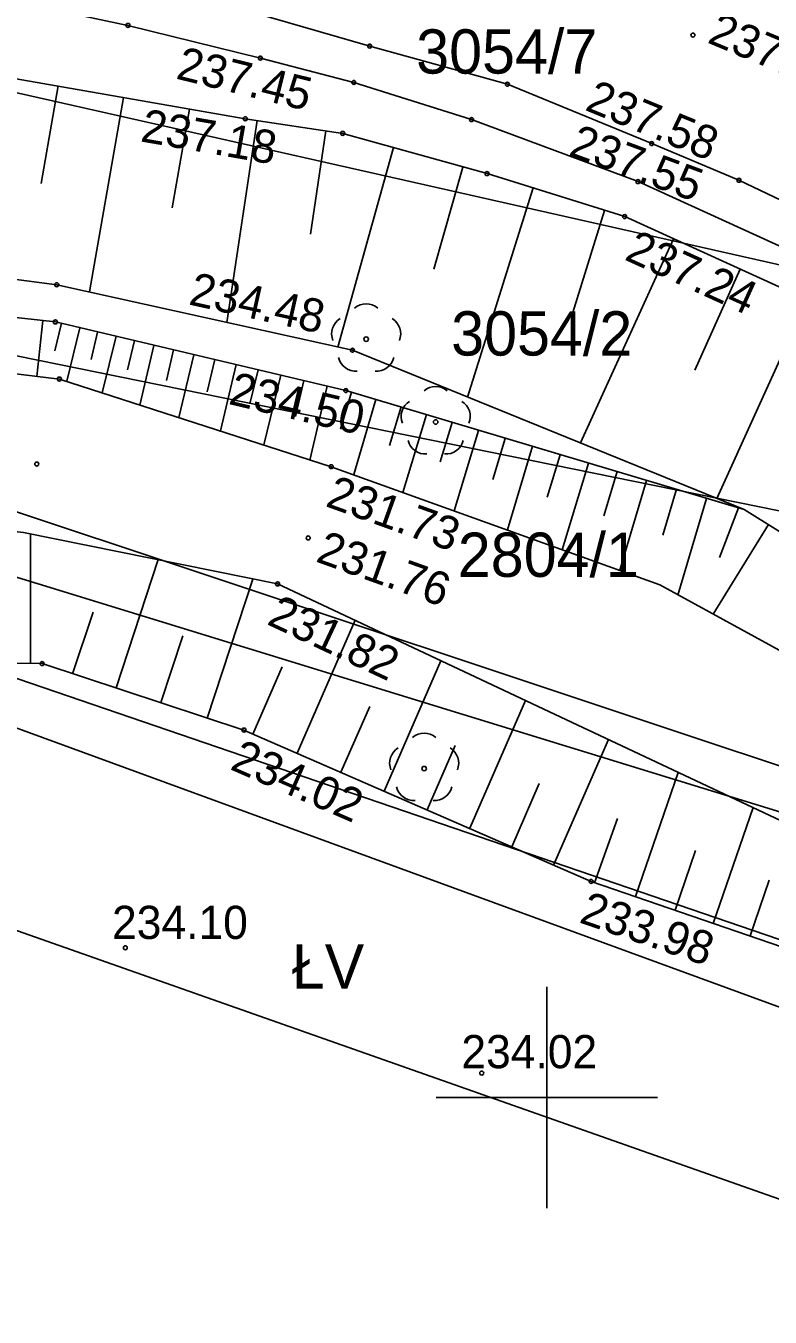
# Model space of a CAD drawing. Extents: x 6596400 to 6597200, y 5539751 to 5540251.
# Drawn here: x 6596788.23 to 6596805.04, y 5540046.04 to 5540075.21 of the extents above; entities that cross this region are included whole.
import ezdxf

# ---------------------------------------------------------------- set-up
doc = ezdxf.new("R2010")
doc.units = 0
for name, color, linetype in [('000 Inne (niezydentyfikowane)', 7, 'Continuous'), ('140-Punkty robocze', 7, 'Continuous'), ('209-oznaczenie konturu klasyfikacyjnego', 7, 'Continuous'), ('211-numer działki ewidencyjnej', 7, 'Continuous'), ('217-kontur klasyfikacyjny', 7, 'Continuous'), ('218-kontur użytku gruntowego', 7, 'Continuous'), ('219-działka ewidencyjna', 7, 'Continuous'), ('bariera ochronna', 7, 'Continuous'), ('drzewo liściaste', 7, 'Continuous'), ('jezdnia', 7, 'Continuous'), ('Linia obszaru zagospodarowania terenu', 7, 'Continuous'), ('pikieta sztuczna', 7, 'Continuous'), ('pikieta sztuczna-Atr2', 7, 'Continuous'), ('rów melioracyjny (poligon)', 7, 'Continuous'), ('skarpa umocniona', 7, 'Continuous'), ('Wstawianie ramki sekcyjnej z opisem', 7, 'Continuous'), ('Zakres', 7, 'Continuous')]:
    doc.layers.add(name, color=color, linetype=linetype)

# ---------------------------------------------------------------- blocks, each defined once
blk = doc.blocks.new('OP021')
blk.add_circle((0, 0), 0.05)
for centre, start, end in [((0, 0.4), 49.272, 130.728), ((-0.38, 0.124), 121.308, 202.548), ((0.38, 0.124), 337.452, 58.692), ((-0.235, -0.324), 193.221, 274.871), ((0.235, -0.324), 265.129, 346.779)]:
    blk.add_arc(centre, 0.4, start, end)
blk = doc.blocks.new('RAMKA500K')
for p, q in [((0, 48.5), (0, 53.5)), ((400, 48.5), (400, 53.5)), ((0, 51), (2.5, 51)), ((397.5, 51), (400, 51))]:
    blk.add_line(p, q)
blk = doc.blocks.new('PW01')
blk.add_circle((0, 0), 0.045)
blk = doc.blocks.new('PIKIETA')
blk.add_circle((0, 0), 0.045)

msp = doc.modelspace()

# ---------------------------------------------------------------- linework, layer by layer
at = {"layer": '000 Inne (niezydentyfikowane)'}
for p, q in [((6596788.96, 5540073.85), (6596788.58, 5540071.65)), ((6596790.44, 5540073.59), (6596789.67, 5540069.2)), ((6596791.93, 5540073.33), (6596791.54, 5540071.1)), ((6596793.46, 5540073.07), (6596792.77, 5540068.51)), ((6596795.01, 5540072.84), (6596794.66, 5540070.5)), ((6596796.54, 5540072.46), (6596795.28, 5540067.95)), ((6596798.1, 5540072.02), (6596797.45, 5540069.71)), ((6596799.69, 5540071.55), (6596798.21, 5540066.82)), ((6596801.3, 5540071.04), (6596800.55, 5540068.61)), ((6596802.86, 5540070.4), (6596800.76, 5540065.79)), ((6596804.37, 5540069.71), (6596803.34, 5540067.43)), ((6596805.88, 5540069.03), (6596803.84, 5540064.53)), ((6596788.62, 5540068.55), (6596788.48, 5540067.29)), ((6596789.04, 5540068.49), (6596788.89, 5540067.87)), ((6596789.45, 5540068.39), (6596789.16, 5540067.18)), ((6596789.85, 5540068.29), (6596789.71, 5540067.67)), ((6596790.27, 5540068.2), (6596789.96, 5540066.92)), ((6596790.69, 5540068.1), (6596790.53, 5540067.44)), ((6596791.12, 5540067.99), (6596790.81, 5540066.64)), ((6596791.57, 5540067.89), (6596791.41, 5540067.2)), ((6596792.03, 5540067.78), (6596791.69, 5540066.36)), ((6596792.5, 5540067.67), (6596792.33, 5540066.94)), ((6596792.98, 5540067.56), (6596792.63, 5540066.06)), ((6596793.48, 5540067.44), (6596793.29, 5540066.67)), ((6596793.99, 5540067.32), (6596793.61, 5540065.74)), ((6596794.51, 5540067.2), (6596794.32, 5540066.38)), ((6596795.04, 5540067.07), (6596794.65, 5540065.4)), ((6596795.59, 5540066.93), (6596795.34, 5540066.1)), ((6596796.14, 5540066.77), (6596795.64, 5540065.07)), ((6596796.71, 5540066.6), (6596796.45, 5540065.73)), ((6596797.28, 5540066.43), (6596796.75, 5540064.67)), ((6596797.86, 5540066.25), (6596797.59, 5540065.36)), ((6596798.46, 5540066.07), (6596797.91, 5540064.25)), ((6596799.06, 5540065.89), (6596798.78, 5540064.96)), ((6596799.68, 5540065.71), (6596799.11, 5540063.82)), ((6596800.3, 5540065.52), (6596800.01, 5540064.56)), ((6596800.94, 5540065.33), (6596800.35, 5540063.37)), ((6596801.59, 5540065.14), (6596801.29, 5540064.14)), ((6596802.25, 5540064.94), (6596801.65, 5540062.91)), ((6596802.93, 5540064.74), (6596802.62, 5540063.7)), ((6596803.61, 5540064.53), (6596802.96, 5540062.35)), ((6596804.33, 5540064.32), (6596803.9, 5540063.2)), ((6596805.01, 5540063.94), (6596803.76, 5540061.92)), ((6596788.34, 5540060.8), (6596788.34, 5540063.73)), ((6596790.27, 5540060.25), (6596791.22, 5540063.15)), ((6596792.33, 5540059.57), (6596793.36, 5540062.71)), ((6596789.29, 5540060.57), (6596789.75, 5540061.96)), ((6596794.36, 5540058.78), (6596795.67, 5540061.78)), ((6596791.28, 5540059.92), (6596791.78, 5540061.43)), ((6596793.36, 5540059.21), (6596794.02, 5540060.73)), ((6596796.33, 5540057.92), (6596797.61, 5540060.86)), ((6596798.26, 5540057.08), (6596799.52, 5540059.97)), ((6596795.35, 5540058.35), (6596796, 5540059.83)), ((6596800.15, 5540056.25), (6596801.39, 5540059.09)), ((6596797.3, 5540057.5), (6596797.93, 5540058.95)), ((6596799.21, 5540056.66), (6596799.83, 5540058.09)), ((6596802, 5540055.54), (6596802.97, 5540058.34)), ((6596803.76, 5540054.93), (6596804.66, 5540057.55)), ((6596801.08, 5540055.85), (6596801.6, 5540057.3)), ((6596802.9, 5540055.23), (6596803.36, 5540056.58)), ((6596804.59, 5540054.65), (6596805.02, 5540055.91))]:
    msp.add_line(p, q, dxfattribs=at)
at = {"layer": '217-kontur klasyfikacyjny'}
msp.add_lwpolyline([(6596806.51, 5540052.58), (6596787.06, 5540059.7)], dxfattribs=at)
at = {"layer": '218-kontur użytku gruntowego'}
for points in [[(6596806.19, 5540069.6), (6596785.82, 5540074.19)], [(6596785.82, 5540074.19), (6596806.19, 5540069.6)], [(6596786.16, 5540068.13), (6596805.25, 5540064.25)], [(6596805.25, 5540064.25), (6596786.16, 5540068.13)], [(6596807.71, 5540056.7), (6596786.08, 5540063.35)], [(6596786.08, 5540063.35), (6596807.71, 5540056.7)], [(6596806.51, 5540052.58), (6596787.06, 5540059.7)], [(6596787.06, 5540059.7), (6596806.51, 5540052.58)]]:
    msp.add_lwpolyline(points, dxfattribs=at)
at = {"layer": '219-działka ewidencyjna'}
for points in [[(6596806.19, 5540069.6), (6596785.82, 5540074.19)], [(6596805.25, 5540064.25), (6596786.16, 5540068.13)], [(6596807.71, 5540056.7), (6596786.08, 5540063.35)], [(6596806.51, 5540052.58), (6596787.06, 5540059.7)]]:
    msp.add_lwpolyline(points, dxfattribs=at)
at = {"layer": 'bariera ochronna'}
msp.add_lwpolyline([(6596774.86, 5540078.28), (6596785.35, 5540076.32), (6596790.54, 5540075.22), (6596793.53, 5540074.48), (6596795.64, 5540073.93), (6596798.3, 5540073.09), (6596802.06, 5540071.69), (6596807.84, 5540069.06), (6596812.67, 5540066.17), (6596814.81, 5540064.78), (6596821.33, 5540060.18), (6596825.095, 5540057.67)], dxfattribs=at)
at = {"layer": 'jezdnia'}
msp.add_lwpolyline([(6596748.72, 5540084.9), (6596758.31, 5540082.61), (6596767.09, 5540080.95), (6596776.43, 5540079.11), (6596785.57, 5540077.35), (6596790.64, 5540076.33), (6596793.76, 5540075.4), (6596796, 5540074.75), (6596799.11, 5540073.89), (6596802.37, 5540072.55), (6596804.34, 5540071.72), (6596806.42, 5540070.73), (6596808.2, 5540069.72), (6596810.28, 5540068.61), (6596812.76, 5540067.19), (6596815.5, 5540065.85), (6596818.95, 5540063.45), (6596822.11, 5540061.14), (6596825.559, 5540058.298)], dxfattribs=at)
at = {"layer": 'Linia obszaru zagospodarowania terenu'}
for points in [[(6596720.263, 5540058.387), (6596728.96, 5540057.84), (6596731.45, 5540057.76), (6596731.02, 5540064.64), (6596745.49, 5540064.58), (6596746.99, 5540056.99), (6596772.84, 5540062.25), (6596786.21, 5540064.83), (6596807.99, 5540057.58), (6596818.837, 5540049.192)], [(6596816.371, 5540045.853), (6596805.78, 5540054.39), (6596786.09, 5540061.13), (6596752.3, 5540048.46), (6596750.16, 5540045.43), (6596750.4, 5540037.69), (6596745.15, 5540037.73), (6596747.098, 5540030.366)]]:
    msp.add_lwpolyline(points, dxfattribs=at)
at = {"layer": 'rów melioracyjny (poligon)'}
for points in [[(6596820.208, 5540051.05), (6596817.24, 5540053.08), (6596812.31, 5540056.77), (6596808.36, 5540059.4), (6596802.55, 5540062.58), (6596795.13, 5540065.25), (6596788.99, 5540067.23), (6596782.3, 5540068.04), (6596775.52, 5540068.1), (6596768.51, 5540067.33), (6596764.82, 5540065.79), (6596761.35, 5540063.62), (6596758.63, 5540061.34), (6596754.58, 5540058.6), (6596752.07, 5540056.28), (6596746.75, 5540055.19), (6596741.65, 5540054.82), (6596742.01, 5540050.53), (6596747.46, 5540050.98), (6596751.88, 5540051.19), (6596756.01, 5540053.96), (6596757.53, 5540054.97), (6596761.73, 5540059.12)], [(6596761.73, 5540059.12), (6596765.87, 5540062.28), (6596769.5, 5540063.71), (6596775.27, 5540065.15), (6596782.49, 5540064.38), (6596788.18, 5540063.76), (6596793.92, 5540062.6), (6596807.97, 5540055.99), (6596815, 5540051.7), (6596818.611, 5540048.887)]]:
    msp.add_lwpolyline(points, dxfattribs=at)
at = {"layer": 'skarpa umocniona'}
msp.add_lwpolyline([(6596784.99, 5540074.54), (6596793.19, 5540073.11), (6596795.39, 5540072.78), (6596798.65, 5540071.87), (6596801.76, 5540070.9), (6596807.63, 5540068.23), (6596814.53, 5540064.38), (6596821.12, 5540059.92), (6596824.79, 5540057.26), (6596821.61, 5540052.95), (6596817.35, 5540056.24), (6596804.46, 5540064.28), (6596795.61, 5540067.88), (6596788.93, 5540069.36), (6596781.56, 5540070.33)], dxfattribs=at)
msp.add_lwpolyline([(6596784.99, 5540074.54), (6596793.19, 5540073.11), (6596795.39, 5540072.78), (6596798.65, 5540071.87), (6596801.76, 5540070.9), (6596807.63, 5540068.23), (6596814.53, 5540064.38), (6596821.12, 5540059.92), (6596824.79, 5540057.26), (6596821.61, 5540052.95), (6596817.35, 5540056.24), (6596804.46, 5540064.28), (6596795.61, 5540067.88), (6596788.93, 5540069.36), (6596781.56, 5540070.33)], dxfattribs=at)
for points in [[(6596781.29, 5540069.35), (6596788.9, 5540068.52), (6596795.46, 5540066.97), (6596804.46, 5540064.28), (6596817.35, 5540056.24), (6596821.61, 5540052.95), (6596820.21, 5540051.05), (6596817.24, 5540053.08), (6596812.31, 5540056.77), (6596808.36, 5540059.4), (6596802.55, 5540062.58), (6596795.13, 5540065.25), (6596788.99, 5540067.23), (6596782.3, 5540068.04), (6596775.52, 5540068.1), (6596768.51, 5540067.33), (6596764.82, 5540065.79), (6596761.35, 5540063.62), (6596758.63, 5540061.34), (6596756.16, 5540061.25), (6596760.14, 5540064.35), (6596763.69, 5540066.4), (6596768.63, 5540068.26), (6596775.9, 5540069.36)], [(6596781.29, 5540069.35), (6596788.9, 5540068.52), (6596795.46, 5540066.97), (6596804.46, 5540064.28), (6596817.35, 5540056.24), (6596821.61, 5540052.95), (6596820.21, 5540051.05), (6596817.24, 5540053.08), (6596812.31, 5540056.77), (6596808.36, 5540059.4), (6596802.55, 5540062.58), (6596795.13, 5540065.25), (6596788.99, 5540067.23), (6596782.3, 5540068.04), (6596775.52, 5540068.1), (6596768.51, 5540067.33), (6596764.82, 5540065.79), (6596761.35, 5540063.62), (6596758.63, 5540061.34), (6596756.16, 5540061.25), (6596760.14, 5540064.35), (6596763.69, 5540066.4), (6596768.63, 5540068.26), (6596775.9, 5540069.36)], [(6596782.49, 5540064.38), (6596788.18, 5540063.76), (6596793.92, 5540062.6), (6596807.97, 5540055.99), (6596815, 5540051.7), (6596818.61, 5540048.89), (6596817.09, 5540046.82), (6596813.04, 5540049.86), (6596807.32, 5540053.71), (6596801, 5540055.88), (6596793.16, 5540059.3), (6596788.6, 5540060.8), (6596783.73, 5540060.81), (6596779.28, 5540061), (6596774.44, 5540061.86), (6596770.5, 5540060.07), (6596764.63, 5540056.07), (6596761.73, 5540059.12), (6596765.87, 5540062.28), (6596769.5, 5540063.71), (6596775.27, 5540065.15)], [(6596782.49, 5540064.38), (6596788.18, 5540063.76), (6596793.92, 5540062.6), (6596807.97, 5540055.99), (6596815, 5540051.7), (6596818.61, 5540048.89), (6596817.09, 5540046.82), (6596813.04, 5540049.86), (6596807.32, 5540053.71), (6596801, 5540055.88), (6596793.16, 5540059.3), (6596788.6, 5540060.8), (6596783.73, 5540060.81), (6596779.28, 5540061), (6596774.44, 5540061.86), (6596770.5, 5540060.07), (6596764.63, 5540056.07), (6596761.73, 5540059.12), (6596765.87, 5540062.28), (6596769.5, 5540063.71), (6596775.27, 5540065.15)]]:
    msp.add_lwpolyline(points, close=True, dxfattribs=at)
at = {"layer": 'Zakres'}
msp.add_lwpolyline([(6596822.22, 5540097.5), (6596800.39, 5540105.4), (6596755.76, 5540121.45), (6596697.73, 5540120.74), (6596659.35, 5540133.92), (6596647.64, 5540109.28), (6596697.73, 5540077), (6596721.01, 5540057.77), (6596727.72, 5540045.95), (6596731.95, 5540033.61), (6596741.17, 5540031.18), (6596755.59, 5540029.2), (6596757.85, 5540044.22), (6596787.25, 5540055.04), (6596806.3, 5540048.33), (6596813.97, 5540042.6), (6596833.15, 5540068.58), (6596822.3, 5540077.75)], close=True, dxfattribs=at)

# ---------------------------------------------------------------- block references
at = {"layer": '140-Punkty robocze'}
for p in [(6596790.54, 5540075.22), (6596796, 5540074.75), (6596795.64, 5540073.93), (6596799.11, 5540073.89), (6596798.3, 5540073.09), (6596795.39, 5540072.78), (6596798.65, 5540071.87), (6596804.34, 5540071.72), (6596788.93, 5540069.36), (6596788.9, 5540068.52), (6596788.99, 5540067.23), (6596788.48, 5540065.31), (6596788.6, 5540060.8)]:
    msp.add_blockref('PIKIETA', p, dxfattribs=at)
at = {"layer": 'drzewo liściaste'}
for p in [(6596795.92, 5540068.13), (6596797.49, 5540066.26), (6596797.23, 5540058.43)]:
    msp.add_blockref('OP021', p, dxfattribs=at)
at = {"layer": 'pikieta sztuczna'}
for p in [(6596803.3, 5540075), (6596793.53, 5540074.48), (6596793.19, 5540073.11), (6596802.37, 5540072.55), (6596802.06, 5540071.69), (6596801.76, 5540070.9), (6596795.61, 5540067.88), (6596795.46, 5540066.97), (6596795.13, 5540065.25), (6596794.61, 5540063.64), (6596793.92, 5540062.6), (6596793.16, 5540059.3), (6596801, 5540055.88), (6596790.48, 5540054.38), (6596798.53, 5540051.55)]:
    msp.add_blockref('PW01', p, dxfattribs=at)
at = {"layer": 'Wstawianie ramki sekcyjnej z opisem'}
for p in [(6596400, 5540000), (6596800, 5540000)]:
    msp.add_blockref('RAMKA500K', p, dxfattribs=at)

# ---------------------------------------------------------------- texts
at = {"layer": '209-oznaczenie konturu klasyfikacyjnego'}
msp.add_text('ŁV', height=1, dxfattribs=at).set_placement((6596794.24, 5540053.46))
at = {"layer": '211-numer działki ewidencyjnej'}
for s, p in [('3054/7', (6596797.05, 5540074.13)), ('3054/2', (6596797.84, 5540067.76)), ('2804/1', (6596797.99, 5540062.76))]:
    msp.add_text(s, height=1, dxfattribs=at).set_placement(p)
at = {"layer": 'pikieta sztuczna-Atr2'}
for s, rotation, p in [('237.79', 337.38, (6596803.602, 5540074.838)), ('237.45', 346.099, (6596791.6, 5540074.022)), ('237.58', 337.655, (6596800.835, 5540073.316)), ('237.18', 350.108, (6596790.801, 5540072.601)), ('237.55', 339.578, (6596800.468, 5540072.297)), ('237.24', 335.541, (6596801.729, 5540069.937)), ('234.48', 347.508, (6596791.888, 5540068.918)), ('234.50', 346.706, (6596792.788, 5540066.67)), ('231.73', 340.209, (6596794.976, 5540064.364)), ('231.76', 340.209, (6596794.756, 5540063.114)), ('231.82', 334.805, (6596793.651, 5540061.701)), ('234.02', 336.432, (6596792.82, 5540058.423)), ('233.98', 341.05, (6596800.706, 5540054.961))]:
    msp.add_text(s, height=0.75, rotation=rotation, dxfattribs=at).set_placement(p)
for s, p in [('234.10', (6596790.18, 5540054.58)), ('234.02', (6596798.07, 5540051.66))]:
    msp.add_text(s, height=0.75, dxfattribs=at).set_placement(p)

doc.saveas('drawing.dxf')
